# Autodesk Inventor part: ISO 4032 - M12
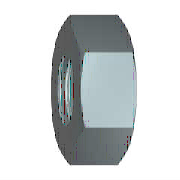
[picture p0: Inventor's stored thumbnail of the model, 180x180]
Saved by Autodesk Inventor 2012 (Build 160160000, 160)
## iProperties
Company: CAD-Verlag
Comments: To add or edit properties for Autodesk Inventor files, use iProperties.
Shininess: 64.0
Length Units: 11269
Angle Units: 11279
Time Units: 11290
Mass Units: 11283
Length Display Precision: 3
Angle Display Precision: 2
Compacted: True
Alert: To add or edit properties for Autodesk Inventor files, use iProperties.
Created: 2004-09
Part Number: ISO 4032 - M12
Vendor: Autodesk Inc.
Document SubType Name: Modeling
Designer: Greiling
Material: Standard
Description: Sechskantmutter
Standard: ISO 4032
Size Designation: M12
Density: 1 g/cm^3
Density: 0.0
Volumn: 0.0
Area: 0.0
PropertySet Name: Model Information
Control State: 0
Master: False
Checked Out: False
EGR: 1
Author: Jürgen Kronas
Revision Number: 8
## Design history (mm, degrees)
sketch "Skizze1"
  geometry: L1 (-10.392, 0)-(-5.196, 9); L2 (-5.196, 9)-(5.196, 9); L3 (5.196, 9)-(10.392, 0); L4 (10.392, 0)-(5.196, -9); L5 (5.196, -9)-(-5.196, -9); L6 (-5.196, -9)-(-10.392, 0); 2 further points
  constraints: 12 end point, 1 coincident, 1 horizontal, 11 other
  dimensions: "d0" = 20.78461 distance of L3.end L1.start (= 1.1547 x SW)
extrude "Körper" new body sketch "Skizze1" distance "d1" = 10.8 (= KOH); taper "d2" = 0 deg
revolve "Fase1" stored, may be unused: angle "d7" = 90 deg
sketch "Skizze3"
  geometry: A1 r 9 centre (0, 0) between (-4.5, -7.794) and (4.5, -7.794) reference; 1 further point
  constraints: 1 coincident
hole "Gewinde" sketch "Skizze3" diameter "d25" = 10.106; stored, may be unused: countersink angle "d29" = 82 deg, drill point angle "d31" = 118 deg; dims "d26" = 6, "d27" = 4, "d28" = 2, "d30" = 8
node "Volumenkörper1"
node "Volumenkörpern"
node "Oberflächenkörpern"
chamfer "Fase2" distance "d8" = 0.94722 (= -0.5 x GD1 + 0.5 x NND); stored, may be unused: angle "d9" = 30 deg, second distance "d40" = 0.94722 (= -0.5 x GD1 + 0.5 x NND)
chamfer "Fase3" distance "d10" = 0.94722 (= -0.5 x GD1 + 0.5 x NND); stored, may be unused: angle "d11" = 30 deg, second distance "d41" = 0.94722 (= -0.5 x GD1 + 0.5 x NND)
sketch "Skizze2"
  geometry: L1 (0, 5.196)-(0, 10.392) reference; L2 (0, 10.392)-(10.8, 10.392) reference; L3 (10.8, 5.196)-(10.8, 10.392) reference; L4 (-1.08, 0)-(14.04, 0) reference; L5 (0.804, 10.392)-(0, 9); L6 (9.996, 10.392)-(10.8, 9)
  constraints: 4 end point, 4 point on line
  dimensions: "d3" = 30 deg angle of L1 L5 (= ANG1); "d4" = 30 deg angle of L3 L6 (= ANG2); "d5" = 18 diameter of L5.end L4 (= SW0); "d6" = 18 diameter of L6.end L4 (= SW01)
other parameters: "ANG1" = 30 deg [user parameter; used in 1 equation term], "ANG2" = 30 deg [user parameter; used in 1 equation term], "NND" = 12 [user parameter; used in 4 equation terms], "KOH" = 10.8 [user parameter; used in 1 equation term], "SW" = 18 [user parameter; used in 2 equation terms], "SW0" = 18 [user parameter; used in 2 equation terms], "SW01" = 18 (= SW0) [user parameter; used in 1 equation term], "GD1" = 10.10557 (computed from THREADDIA, TPU, TOA) [user parameter; used in 4 equation terms], "d13" = 0, "d14" = 0, "d39" = 0, "E0" = 20.79 (= 1.155 x SW) [user parameter], "THREADDIA" = 12 [user parameter; used in 1 equation term], "TPU" = 1.75 [user parameter; used in 4 equation terms], "GUL" = 0.94722 (= 0.541266 x TPU) [user parameter], "GAL" = 0.94722 (= 0.541266 x TPU) [user parameter], "PTC" = 1.75 (= TPU) [user parameter], "TOA" = 30 deg [user parameter; used in 1 equation term]
